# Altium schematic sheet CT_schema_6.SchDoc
size 430 x 429 mm
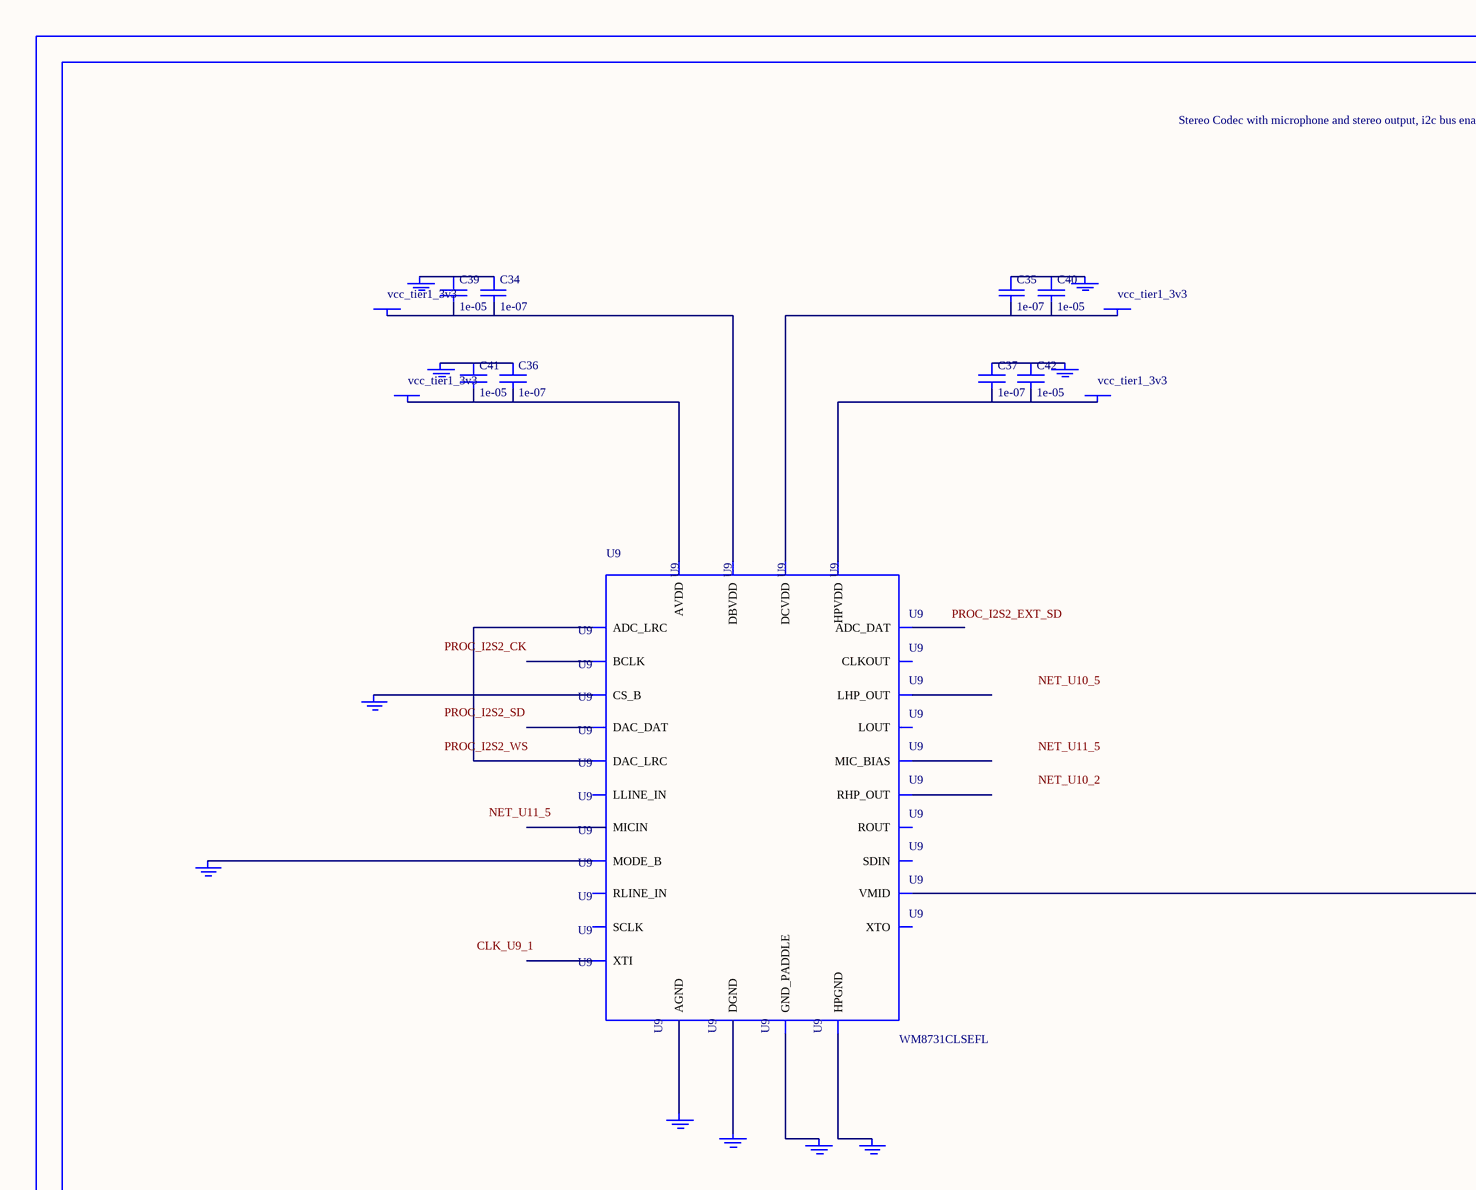
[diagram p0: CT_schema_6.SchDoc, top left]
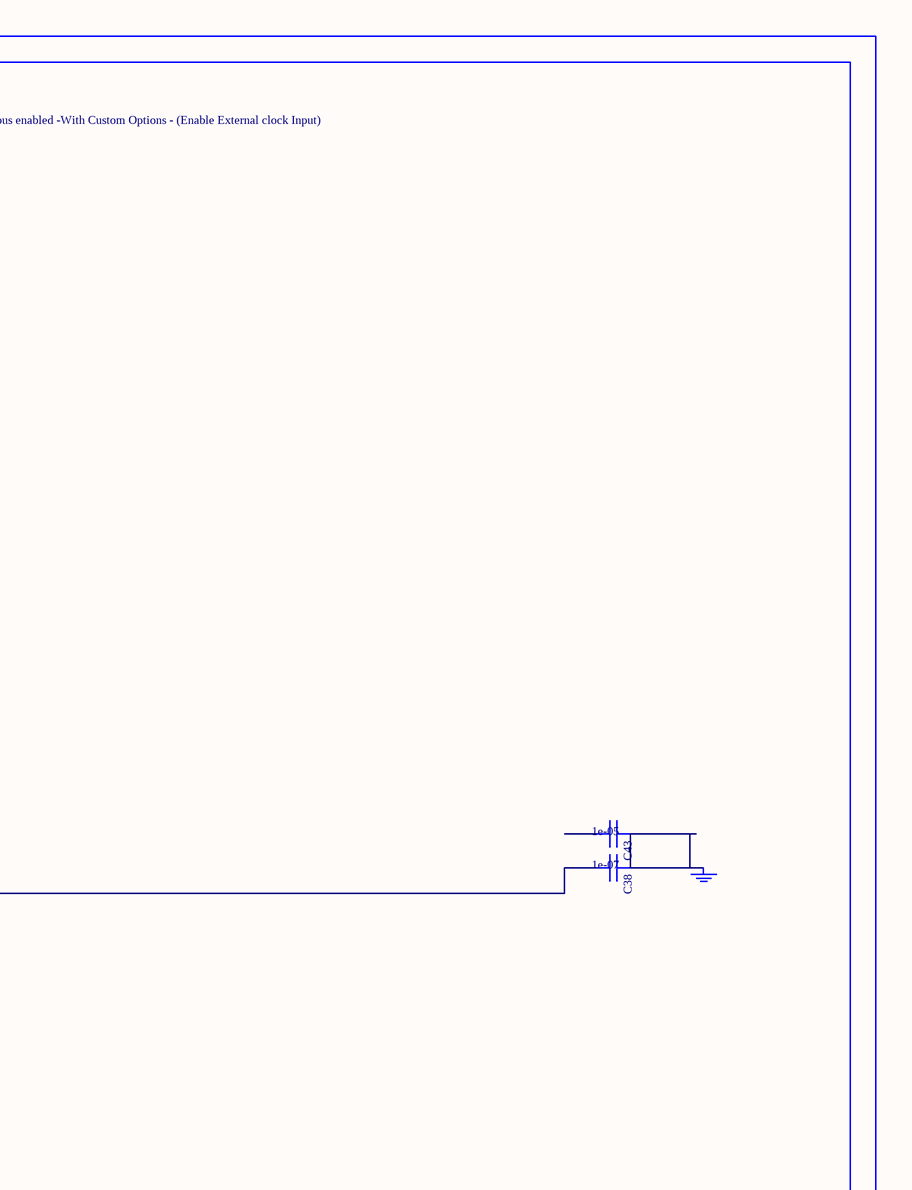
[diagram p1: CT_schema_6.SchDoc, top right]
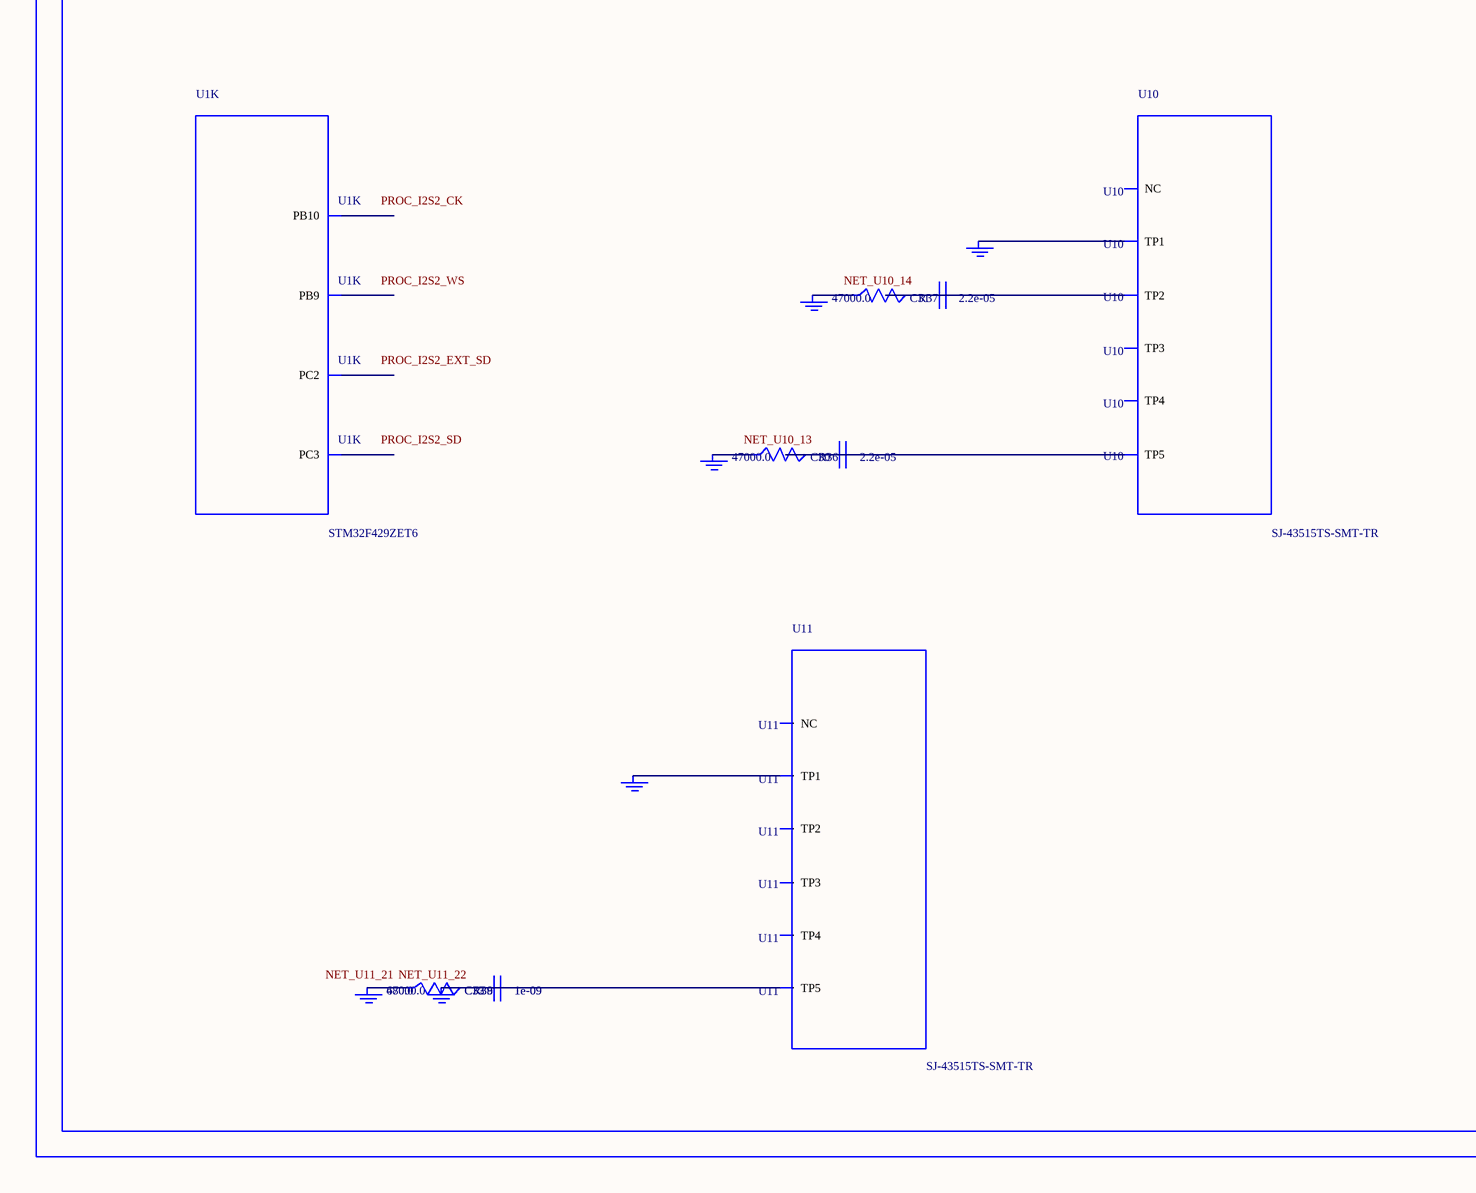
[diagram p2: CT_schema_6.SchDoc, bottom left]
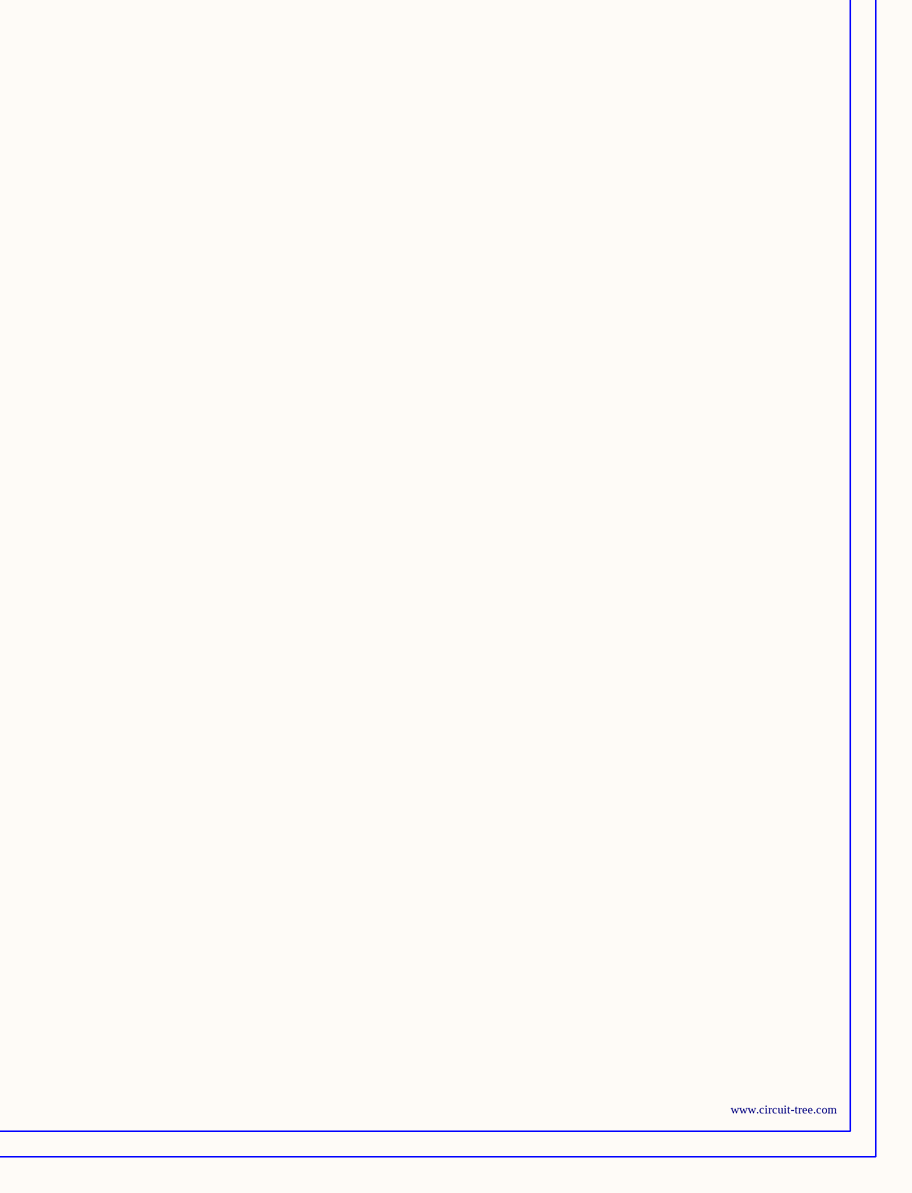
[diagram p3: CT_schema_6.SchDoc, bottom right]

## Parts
BORDER5  (no value)
C30  2.2e-05  [C1210]
C31  2.2e-05  [C1210]
C32  1e-09  [C0402]
C33  1e-09  [C0402]
C34  1e-07  [C0402]
C35  1e-07  [C0402]
C36  1e-07  [C0402]
C37  1e-07  [C0402]
C38  1e-07  [C0402]
C39  1e-05  [C0805]
C40  1e-05  [C0805]
C41  1e-05  [C0805]
C42  1e-05  [C0805]
C43  1e-05  [C0805]
GND_INSTANCE_5_0  (no value)
GND_INSTANCE_5_1  (no value)
GND_INSTANCE_5_2  (no value)
GND_INSTANCE_5_3  (no value)
GND_INSTANCE_5_4  (no value)
GND_INSTANCE_5_5  (no value)
GND_INSTANCE_5_6  (no value)
GND_INSTANCE_5_7  (no value)
GND_INSTANCE_5_8  (no value)
GND_INSTANCE_5_9  (no value)
GND_INSTANCE_5_10  (no value)
GND_INSTANCE_5_11  (no value)
GND_INSTANCE_5_12  (no value)
GND_INSTANCE_5_13  (no value)
GND_INSTANCE_5_14  (no value)
GND_INSTANCE_5_15  (no value)
GND_INSTANCE_5_16  (no value)
POWER_INSTANCE_5_0  vcc_tier1_3v3
POWER_INSTANCE_5_1  vcc_tier1_3v3
POWER_INSTANCE_5_2  vcc_tier1_3v3
POWER_INSTANCE_5_3  vcc_tier1_3v3
R36  47000.0  [R0603]
R37  47000.0  [R0603]
R38  47000.0  [R0603]
R39  680.0  [R0603]
U1  STM32F429ZET6  [LQFP144]  (part K of 11)
U9  WM8731CLSEFL  [QFN-28]
U10  SJ-43515TS-SMT-TR  [SJ-43515TS-SMT-TR]
U11  SJ-43515TS-SMT-TR  [SJ-43515TS-SMT-TR]

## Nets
NetC30_1: C30.1 C30.2 R36.2 U10.5(TP5)
NetC31_1: C31.1 C31.2 R37.2 U10.2(TP2)
NetC32_1: C32.1 C32.2 C33.1 C33.2 GND_INSTANCE_5_16.0(GND) R38.2 R39.2 U11.5(TP5)
NetC34_1: C34.1 C39.1 GND_INSTANCE_5_1.0(GND)
NetC34_2: C34.2 C39.2 POWER_INSTANCE_5_1.0(PWR) U9.5(DBVDD)
NetC35_1: C35.1 C40.1 GND_INSTANCE_5_0.0(GND)
NetC35_2: C35.2 C40.2 POWER_INSTANCE_5_0.0(PWR) U9.3(DCVDD)
NetC36_1: C36.1 C41.1 GND_INSTANCE_5_4.0(GND)
NetC36_2: C36.2 C41.2 POWER_INSTANCE_5_3.0(PWR) U9.18(AVDD)
NetC37_1: C37.1 C42.1 GND_INSTANCE_5_2.0(GND)
NetC37_2: C37.2 C42.2 POWER_INSTANCE_5_2.0(PWR) U9.12(HPVDD)
NetC38_1: C38.1 C43.1 GND_INSTANCE_5_5.0(GND)
NetC38_2: C38.2 U9.20(VMID)
NetGND_INSTANCE_5_3_0: GND_INSTANCE_5_3.0(GND) U9.15(HPGND)
NetGND_INSTANCE_5_6_0: GND_INSTANCE_5_6.0(GND) U9.25(MODE_B)
NetGND_INSTANCE_5_7_0: GND_INSTANCE_5_7.0(GND) U9.26(CS_B)
NetGND_INSTANCE_5_8_0: GND_INSTANCE_5_8.0(GND) U9.29(GND_PADDLE)
NetGND_INSTANCE_5_9_0: GND_INSTANCE_5_9.0(GND) U9.4(DGND)
NetGND_INSTANCE_5_10_0: GND_INSTANCE_5_10.0(GND) U9.19(AGND)
NetGND_INSTANCE_5_11_0: GND_INSTANCE_5_11.0(GND) U10.1(TP1)
NetGND_INSTANCE_5_12_0: GND_INSTANCE_5_12.0(GND) R37.1
NetGND_INSTANCE_5_13_0: GND_INSTANCE_5_13.0(GND) R36.1
NetGND_INSTANCE_5_14_0: GND_INSTANCE_5_14.0(GND) U11.1(TP1)
NetGND_INSTANCE_5_15_0: GND_INSTANCE_5_15.0(GND) R38.1 R39.1
NetU9_9: U9.9(DAC_LRC) U9.11(ADC_LRC)

Not connected (* = marked no-connect by the designer): C43 2; U1 28(PC2) 29(PC3) 69(PB10) 140(PB9); U9 1(XTI) 2(XTO) 6(CLKOUT) 7(BCLK) 8(DAC_DAT) 10(ADC_DAT) 13(LHP_OUT) 14(RHP_OUT) 16(LOUT) 17(ROUT) 21(MIC_BIAS) 22(MICIN) 23(RLINE_IN) 24(LLINE_IN) 27(SDIN) 28(SCLK); U10 3(TP3) 4(TP4) 6(NC); U11 2(TP2) 3(TP3) 4(TP4) 6(NC)

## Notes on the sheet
- Labels drawn without touching a wire or pin: CLK_U9_1, NET_U10_2, NET_U10_5, NET_U10_13, NET_U10_14, NET_U11_5, NET_U11_21, NET_U11_22, PROC_I2S2_CK, PROC_I2S2_EXT_SD, PROC_I2S2_SD, PROC_I2S2_WS

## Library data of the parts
BORDER5 = BORDER_PAGE5
C30 C31 = C1210C224K5RACTU
C32 C33 = C0402C102K3RAC
C34-C38 = C0402C104K3RACTU
C39-C43 = C0805C106K8RACTU
GND_INSTANCE_5_0-GND_INSTANCE_5_16 = GND
POWER_INSTANCE_5_0-POWER_INSTANCE_5_3 = PWR
R36-R38 = RC0603JR-0747KL
R39 = RC0603JR-07680RL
